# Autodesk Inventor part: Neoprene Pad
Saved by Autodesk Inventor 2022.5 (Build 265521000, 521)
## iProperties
Created: 2024-07
Part Number: Neoprene Pad
Material: Generic
Document SubType Name: Modeling
Designer: AdminForWorker
Density: 1 g/cm^3
Appearance: Default
Title: Neoprene Pad
Author: AdminForWorker
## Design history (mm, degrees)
feature "Neoprene Pad"
body "Solid1"
